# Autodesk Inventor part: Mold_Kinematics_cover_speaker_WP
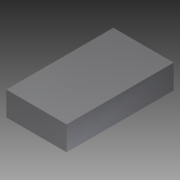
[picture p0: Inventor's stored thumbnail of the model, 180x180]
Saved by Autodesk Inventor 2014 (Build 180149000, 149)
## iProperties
Created: 2009-12
Part Number: Mold_Kinematics_cover_speaker_WP
Document SubType Name: Modeling
Designer: gaom
Density: 1 g/cm^3
Material: Generic
Appearance: Light Gray
d1: 79.000 mm
d2: 79.000 mm
d3: 140.000 mm
d4: 140.000 mm
d5: 63.000 mm
d6: 0.00 deg
Xmin: -79.000 mm
Ymin: -140.000 mm
Zmin: -31.500 mm
Xmax: 79.000 mm
Ymax: 140.000 mm
Zmax: 31.500 mm
d0: -31.500 mm
Author: gaom
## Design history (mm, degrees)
sketch "Sketch1"
  geometry: L1 (-79, 140)-(79, 140); L2 (79, 140)-(79, -140); L3 (79, -140)-(-79, -140); L4 (-79, -140)-(-79, 140); 1 further point
  constraints: 8 end point, 2 parallel, 1 horizontal, 1 perpendicular, 1 other
  dimensions: "d1" = 79 distance from line of L4 point (0, 0) (= -Xmin); "d2" = 79 distance from line of L2 point (0, 0) (= Xmax); "d3" = 140 distance from line of L3 point (0, 0) (= -Ymin); "d4" = 140 distance from line of L1 point (0, 0) (= Ymax)
extrude "Extrusion1" join sketch "Sketch1" distance "d5" = 63 (= Zmax - Zmin); taper "d6" = 0 deg
body "Solid1"
other parameters: "Xmin" = -79 [user parameter; used in 1 equation term], "Ymin" = -140 [user parameter; used in 1 equation term], "Zmin" = -31.5 [user parameter; used in 1 equation term], "Xmax" = 79 [user parameter; used in 1 equation term], "Ymax" = 140 [user parameter; used in 1 equation term], "Zmax" = 31.5 [user parameter; used in 1 equation term], "d0" = -31.5
